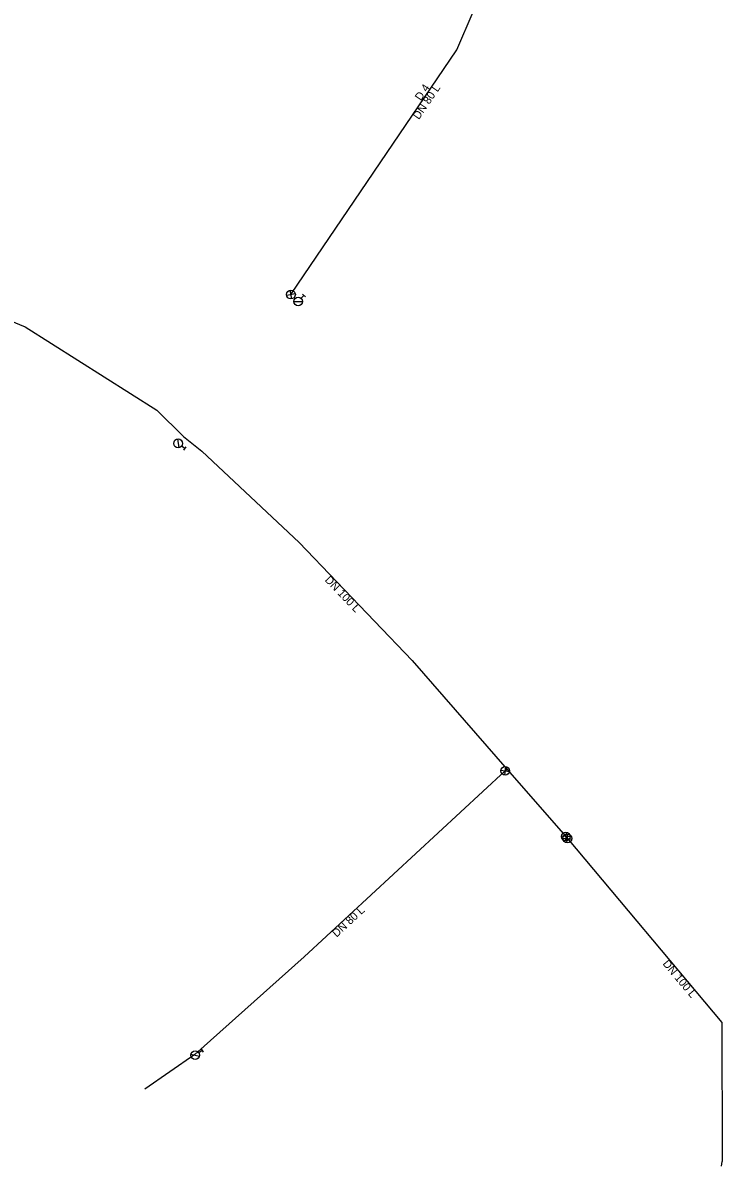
# Model space of a CAD drawing. Extents: x -600635 to -600187, y -1203951 to -1203569.
# Drawn here: x -600453.9 to -600374.3, y -1203950.9 to -1203820.8 of the extents above; entities that cross this region are included whole.
import ezdxf

# ---------------------------------------------------------------- set-up
doc = ezdxf.new("R2010")
doc.units = 0
for name, color, linetype in [('Default', 7, 'Continuous'), ('hydrant_v_majetku_nebo_provozovany', 7, 'Continuous'), ('popisy_rad', 7, 'Continuous'), ('rad_v_majetku', 7, 'Continuous'), ('uzaver_v_majetku_nebo_provozovany', 7, 'Continuous')]:
    doc.layers.add(name, color=color, linetype=linetype)

# ---------------------------------------------------------------- blocks, each defined once
blk = doc.blocks.new('MoSymbol 2')
at = {"layer": 'Default'}
for p, q in [((-0.000035, -0.000035), (0.000035, 0.000035)), ((0.000035, -0.000035), (-0.000035, 0.000035))]:
    blk.add_line(p, q, dxfattribs=at)
for radius in [0.00005, 0.0000025]:
    blk.add_circle((0, 0), radius, dxfattribs=at)
blk = doc.blocks.new('MoSymbol 3')
at = {"layer": 'Default'}
for p, q in [((-0.000036, -0.000036), (0.000036, 0.000036)), ((-0.000023, 0.000095), (0.000023, 0.000095)), ((0, 0.000095), (0, 0.00005))]:
    blk.add_line(p, q, dxfattribs=at)
blk.add_circle((0, 0), 0.00005, dxfattribs=at)

msp = doc.modelspace()

# ---------------------------------------------------------------- linework, layer by layer
at = {"layer": 'rad_v_majetku'}
for p, q in [((-600398.75, -1203905.75), (-600398.99, -1203905.91)), ((-600398.75, -1203905.75), (-600392.08, -1203913.38)), ((-600392.08, -1203913.38), (-600391.91, -1203913.61)), ((-600434.31, -1203938.16), (-600440, -1203942.11)), ((-600374.37, -1203950.87), (-600374.3, -1203950.35)), ((-600374.3, -1203949.92), (-600374.3, -1203950.35))]:
    msp.add_line(p, q, dxfattribs=at)
for points in [[(-600423.36, -1203851.75), (-600404.49, -1203823.91), (-600397.06, -1203806.59), (-600395.74, -1203804.12)], [(-600485.04, -1203842.84), (-600467.04, -1203849.9), (-600453.61, -1203855.4), (-600438.63, -1203864.89), (-600435.58, -1203867.87)], [(-600435.58, -1203867.87), (-600433.49, -1203869.55), (-600422.42, -1203879.96), (-600409.57, -1203893.38), (-600398.75, -1203905.75)], [(-600398.99, -1203905.91), (-600421.85, -1203927.07), (-600434.31, -1203938.16)], [(-600391.91, -1203913.61), (-600374.34, -1203934.52), (-600374.3, -1203949.92)]]:
    msp.add_lwpolyline(points, dxfattribs=at)

# ---------------------------------------------------------------- block references
at = {"layer": 'hydrant_v_majetku_nebo_provozovany'}
for p, xscale, yscale, rotation in [((-600422.54, -1203852.53), 9998.75015623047, 9998.750156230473, -43.65884022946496), ((-600436.2, -1203868.67), 9998.750156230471, 9998.75015623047, -127.1911664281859), ((-600434.26, -1203938.24), 9998.75015623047, 9998.750156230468, -57.33144380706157)]:
    msp.add_blockref('MoSymbol 3', p, dxfattribs=dict(at, xscale=xscale, yscale=yscale, rotation=rotation))
at = {"layer": 'uzaver_v_majetku_nebo_provozovany'}
for p, xscale, yscale, rotation in [((-600423.36, -1203851.75), 9998.750156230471, 9998.75015623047, 55.871659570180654), ((-600398.99, -1203905.91), 9998.75015623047, 9998.750156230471, -141.82022535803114), ((-600392.08, -1203913.38), 9998.75015623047, 9998.75015623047, 129.26524450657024), ((-600391.91, -1203913.61), 9998.75015623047, 9998.750156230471, -51.306810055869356)]:
    msp.add_blockref('MoSymbol 2', p, dxfattribs=dict(at, xscale=xscale, yscale=yscale, rotation=rotation))

# ---------------------------------------------------------------- texts
at = {"layer": 'popisy_rad'}
for s, rotation, p in [('DN 80 L', 55.8717, (-600408.81, -1203831.91)), ('D 4', 55.8717, (-600408.58, -1203829.77)), ('DN 100 L', 313.7574, (-600419.57, -1203884.26)), ('DN 80 L', 42.7822, (-600418.17, -1203924.89)), ('DN 100 L', 310.0285, (-600381.12, -1203927.87))]:
    msp.add_text(s, height=0.91, rotation=rotation, dxfattribs=at).set_placement(p)

doc.saveas('drawing.dxf')
